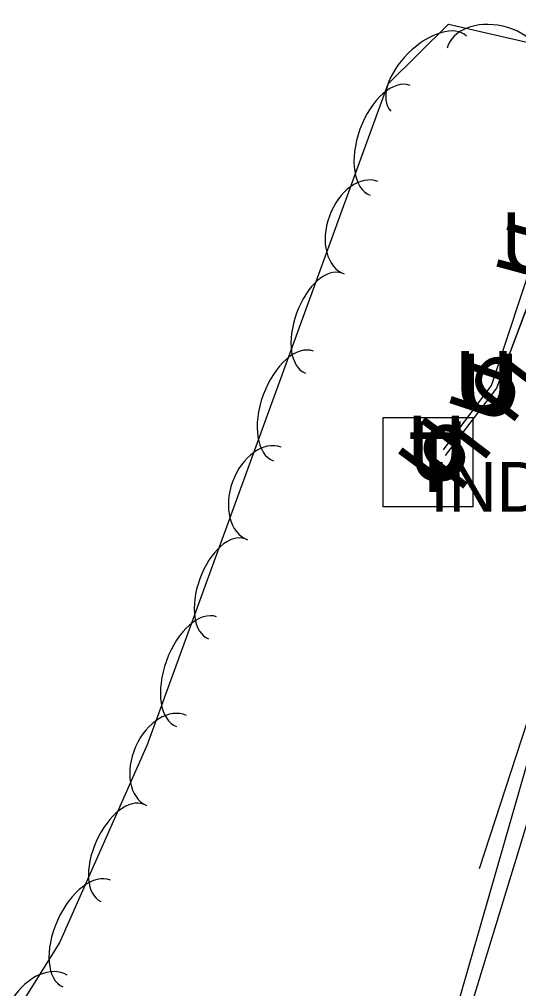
# Model space of a CAD drawing. Extents: x 954793 to 988390, y 1867850 to 1924428.
# Drawn here: x 961177.2 to 961227.4, y 1906452 to 1906549.5 of the extents above; entities that cross this region are included whole.
import ezdxf

# ---------------------------------------------------------------- set-up
doc = ezdxf.new("R2010")
doc.units = 0
for name, color, linetype in [('Default', 7, 'Continuous'), ('S_DITCHLINE', 7, 'Continuous'), ('S_STREAM', 7, 'Continuous'), ('S_TELEPHONE_UTILITIES', 7, 'Continuous'), ('S_TELEPHONE_UTILITIES_ANNOT', 7, 'Continuous'), ('S_TREE', 7, 'Continuous'), ('S_UNDERGROUND_CABLE', 7, 'Continuous')]:
    doc.layers.add(name, color=color, linetype=linetype)

msp = doc.modelspace()

# ---------------------------------------------------------------- linework, layer by layer
at = {"layer": 'S_DITCHLINE'}
for points in [[(961220.793, 1906448.634), (961225.918, 1906466.474), (961231.043, 1906484.314), (961236.167, 1906502.154), (961241.292, 1906519.994), (961246.399, 1906540.223), (961251.506, 1906560.452)], [(961222.128, 1906448.62), (961227.506, 1906466.248), (961232.884, 1906483.877), (961238.262, 1906501.505), (961243.641, 1906519.133), (961249.272, 1906539.147), (961254.903, 1906559.161)]]:
    msp.add_lwpolyline(points, dxfattribs=at)
at = {"layer": 'S_STREAM'}
msp.add_lwpolyline([(961250.811, 1906553.458), (961231.942, 1906490.142), (961223.429, 1906464.06)], dxfattribs=at)
at = {"layer": 'S_TELEPHONE_UTILITIES'}
msp.add_lwpolyline([(961213.778, 1906500.448), (961213.778, 1906509.448), (961222.778, 1906509.448), (961222.778, 1906500.448)], close=True, dxfattribs=at)
at = {"layer": 'S_TREE'}
msp.add_lwpolyline([(961172.546, 1906442.752), (961181.21, 1906456.588), (961190.089, 1906476.565), (961214.287, 1906542.981), (961220.354, 1906548.985), (961229.279, 1906546.937), (961236.191, 1906541.545), (961237.214, 1906525.448), (961232.255, 1906508.853), (961232.718, 1906492.121), (961238.374, 1906480.802), (961236.388, 1906463.948), (961228.45, 1906443.715)], dxfattribs=at)
for centre, major_axis, ratio in [((961225.057, 1906545.461), (-4.83, 1.108), 0.685311), ((961218.34, 1906544.008), (-3.8, -3.761), 0.540699), ((961214.478, 1906537.309), (-2.009, -5.514), 0.55008), ((961211.554, 1906528.52), (-1.696, -4.656), 0.685311), ((961207.781, 1906518.929), (-1.83, -5.023), 0.540699), ((961204.745, 1906510.597), (-2.009, -5.514), 0.55008), ((961201.821, 1906501.808), (-1.696, -4.656), 0.685311), ((961198.049, 1906492.216), (-1.83, -5.023), 0.540699), ((961195.013, 1906483.884), (-2.009, -5.514), 0.55008), ((961191.983, 1906474.961), (-2.012, -4.528), 0.685311), ((961187.56, 1906465.652), (-2.171, -4.886), 0.540699), ((961183.959, 1906457.548), (-2.383, -5.363), 0.55008), ((961179.374, 1906449.166), (-2.63, -4.2), 0.685311)]:
    msp.add_ellipse(centre, major_axis=major_axis, ratio=ratio, start_param=3.141593, end_param=6.283185, dxfattribs=at)
at = {"layer": 'S_UNDERGROUND_CABLE'}
for p, q in [((961230.941, 1906527.732), (961225.188, 1906512.384)), ((961224.656, 1906512.655), (961229.291, 1906526.618)), ((961219.85, 1906506.181), (961224.656, 1906512.655)), ((961225.188, 1906512.384), (961220.019, 1906505.611))]:
    msp.add_line(p, q, dxfattribs=at)
for points in [[(961219.85, 1906506.181), (961224.656, 1906512.655), (961229.291, 1906526.618), (961245.179, 1906585.138), (961262.508, 1906650.282), (961274.327, 1906713.584), (961277.079, 1906742.855), (961276.18, 1906766.431), (961280.477, 1906820.723), (961289.875, 1906871.788), (961287.249, 1906929.103), (961276.233, 1906978.141), (961270.691, 1906999.66), (961269.704, 1907011.394), (961250.98, 1907085.774), (961240.814, 1907120.208), (961192.22, 1907298.688), (961177.296, 1907348.839), (961184.149, 1907354.027)], [(961219.85, 1906506.181), (961224.656, 1906512.655), (961229.291, 1906526.618), (961245.179, 1906585.138), (961262.508, 1906650.282), (961274.327, 1906713.584), (961277.079, 1906742.855), (961276.18, 1906766.431), (961280.477, 1906820.723), (961289.875, 1906871.788), (961287.249, 1906929.103), (961276.233, 1906978.141), (961270.691, 1906999.66), (961269.704, 1907011.394), (961250.98, 1907085.774), (961240.814, 1907120.208), (961192.22, 1907298.688), (961177.296, 1907348.839), (961184.149, 1907354.027)], [(961230.941, 1906527.732), (961225.188, 1906512.384), (961220.019, 1906505.611)], [(961230.941, 1906527.732), (961225.188, 1906512.384), (961220.019, 1906505.611)]]:
    msp.add_lwpolyline(points, dxfattribs=at)

# ---------------------------------------------------------------- texts
at = {"layer": 'Default'}
for rotation, p in [(360, (961225.662, 1906524.073)), (74.81134, (961230.797, 1906522.448)), (360, (961221.027, 1906510.11)), (360, (961221.559, 1906509.839)), (71.63549, (961225.928, 1906508.408)), (232.64577, (961225.367, 1906516.813)), (53.4071, (961219.73, 1906501.75)), (360, (961216.22, 1906503.636)), (360, (961216.389, 1906503.066)), (232.64577, (961220.198, 1906510.041))]:
    msp.add_text('U', height=6, rotation=rotation, dxfattribs=at).set_placement(p)
at = {"layer": 'S_TELEPHONE_UTILITIES'}
msp.add_text('T', height=6, rotation=360, dxfattribs=at).set_placement((961216.341, 1906501.948))
at = {"layer": 'S_TELEPHONE_UTILITIES_ANNOT'}
msp.add_text('INDEPENDENT', height=5, dxfattribs=at).set_placement((961218.506, 1906499.966))

doc.saveas('drawing.dxf')
